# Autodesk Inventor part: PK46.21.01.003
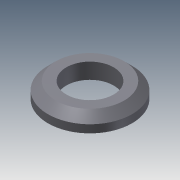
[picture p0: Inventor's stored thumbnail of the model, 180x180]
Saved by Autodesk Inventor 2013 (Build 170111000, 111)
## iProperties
Created: 2005-04
Part Number: PK46.21.01.003
Material: Steel, Mild
Document SubType Name: Modeling
Designer: salex
Manufacturer: Standard
Standards Organization: Custom
Density: 7.86 g/cm^3
Author: salex
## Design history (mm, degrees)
sketch "Эскиз1"
  geometry: C1 r 45 at (0, 0); C2 r 80 at (0, 0)
  constraints: 2 centre point, 1 coincident, 1 other
  dimensions: "d0" = 160 diameter of C2; "d1" = 90 diameter of C1
extrude "Выдавливание1" new body sketch "Эскиз1" distance "d2" = 30; taper "d3" = 0 deg
chamfer "Фаска1" distance "d4" = 15; stored, may be unused: second distance "d5" = 2, angle "d6" = 45 deg
body "Solid1"
